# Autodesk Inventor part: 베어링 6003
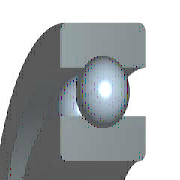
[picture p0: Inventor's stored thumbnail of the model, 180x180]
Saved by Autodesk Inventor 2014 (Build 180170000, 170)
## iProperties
Created: 2012-02
Part Number: 베어링 6003
Material: 강철, 연강
Description: 깊은 그루브 볼 베어링
Document SubType Name: Modeling
Standard: KS B 2023
Designer: mduedu
Standards Organization: KS
Language: ko-KR
Size Designation: 6003 - 17 x 35 x 10
Categories: <MemberInstance><Categories><Category DisplayName="샤프트 부품" InternalName="7f7aeb1f-a693-4053-b835-cee3144e0d98" Mnemonic="SHFT"><Category DisplayName="베어링" Inter
Density: 7.86 g/cm^3
Appearance: Yellow
Mass: 35.231 g
Surface Area: 48.7538 cm^2
Volume: 4.48231 cm^3
IsCustomPart: 1
Author: mduedu
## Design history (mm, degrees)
sketch "스케치" dims "d0" = 4.68 (= -0.26 x WD + 0.26 x BD)
  geometry: L1 (2.66, 13)-(7.34, 13); L2 (5, 13)-(5, 10.66); L3 (5, 13)-(5, 15.34); L4 (3.261, 11.434)-(0, 11.434); L5 (0, 8.5)-(10, 8.5); L6 (3.261, 14.566)-(0, 14.566); L7 (0, 17.5)-(10, 17.5); L8 (10, 8.5)-(10, 11.434); L9 (6.739, 11.434)-(10, 11.434); L10 (6.739, 14.566)-(10, 14.566); L11 (10, 17.5)-(10, 14.566); L12 (-1.4, 0)-(8.4, 0) reference; L13 (0, -0.3)-(0, 5.3) reference
  constraints: 22 end point, 4 point on line, 2 collinear, 2 perpendicular, 2 symmetric about line, 1 midpoint, 1 parallel, 14 other
  dimensions: "d9" = 17 diameter of L5 L12 (= WD); "d11" = 35 diameter of L7 L12 (= BD); "d12" = 10 distance between parallel lines of L8 L13 (= KB); "d13" = 22.868 diameter of L9 L12 (= 0.326 x BD + 0.674 x WD)
revolve "본체" stored, may be unused: angle "d6" = 90 deg
revolve "볼" stored, may be unused: angle "d7" = 90 deg
pattern_circular "IDS_ARRAYBALL[SIMPL:T]" dims angle "d3" = 360 deg
body "Solid1"
fillet "모깎기1" dims "d1" = 0.3 (= KRS)
other parameters: "WD" = 17 [user parameter; used in 5 equation terms], "BD" = 35 [user parameter; used in 5 equation terms], "KB" = 10 [user parameter; used in 1 equation term], "KRS" = 0.3 [user parameter; used in 1 equation term], "d4" = 0, "d5" = 0, "d8" = 0, "d14" = 0, "d15" = 0, "BBA" = 0 [user parameter], "BC0" = 3250000 [user parameter], "BC" = 6050000 [user parameter], "BR" = 17.5 (= 0.5 x BD) [user parameter], "WR" = 8.5 (= 0.5 x WD) [user parameter]
